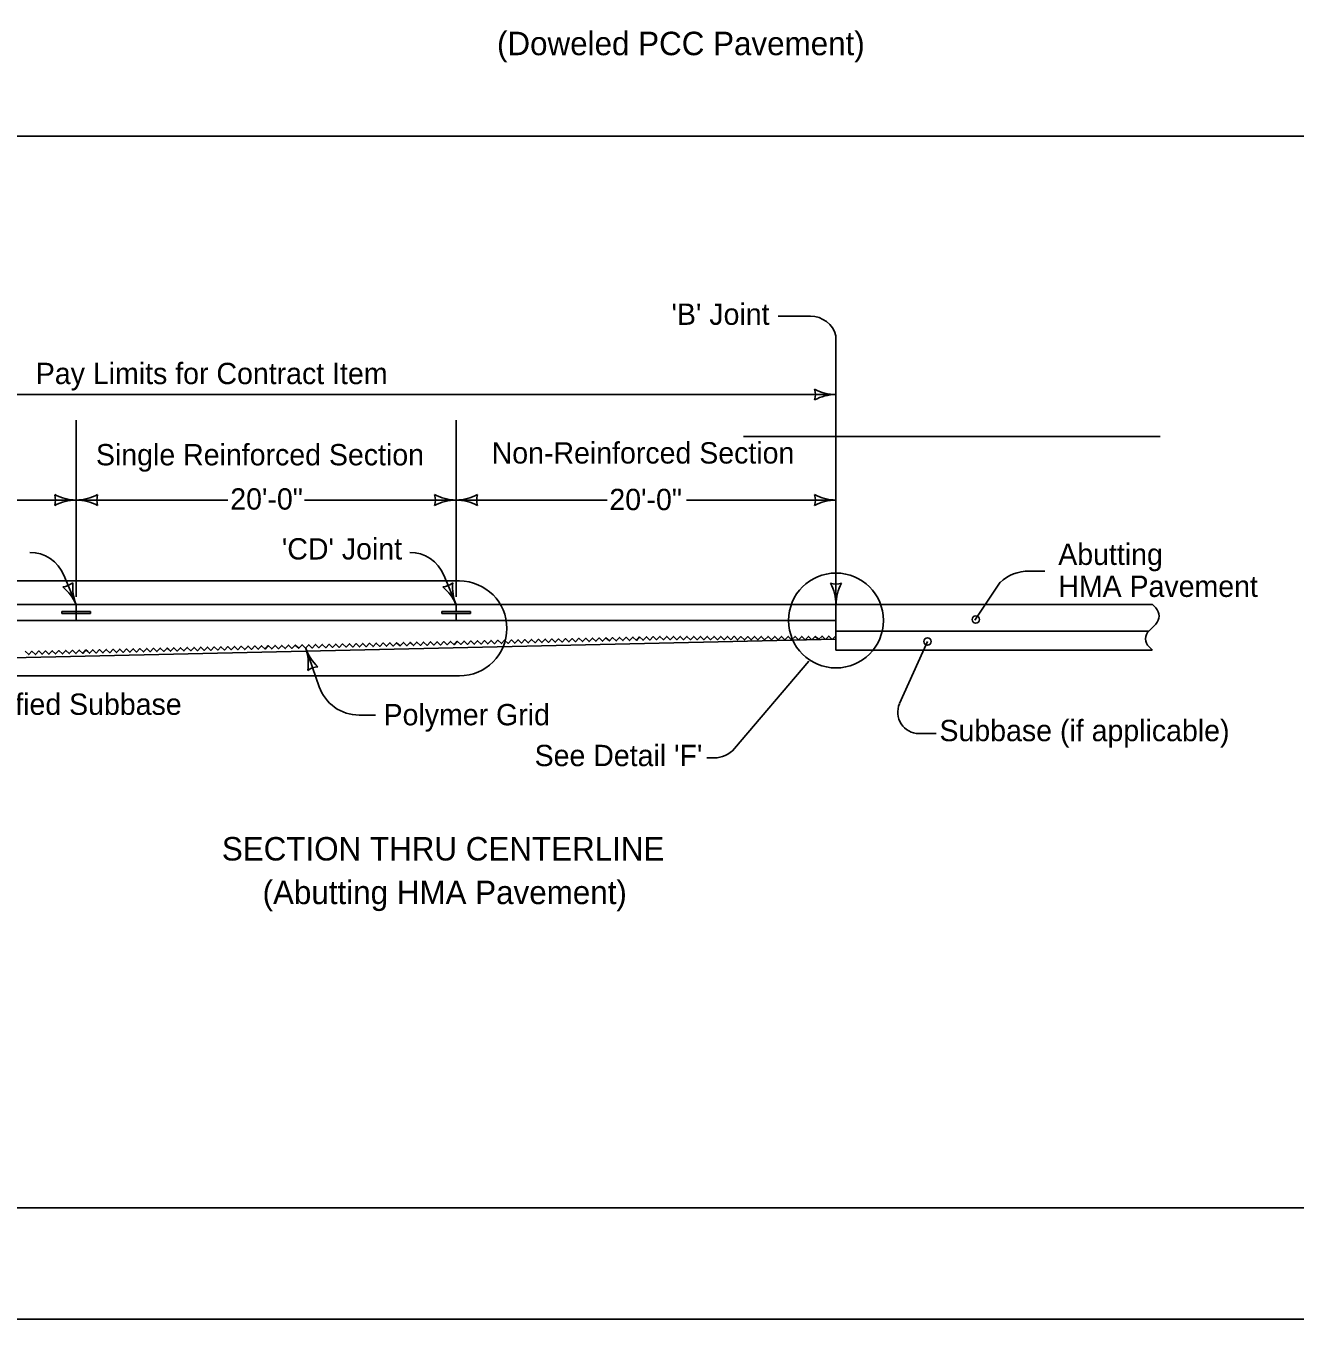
# Model space of a CAD drawing. Extents: x -2135039 to -2120895, y -2139150 to -2136566.
# Drawn here: x -2126883 to -2125693, y -2139150 to -2137937 of the extents above; entities that cross this region are included whole.
import ezdxf

# ---------------------------------------------------------------- set-up
doc = ezdxf.new("R2010")
doc.units = 0
for name, color, linetype in [('dsnDOTLogo', 7, 'Continuous'), ('dsnNonPlotable', 7, 'Continuous'), ('dsnStdDimension', 7, 'Continuous'), ('dsnStdLabel', 7, 'Continuous'), ('dsnStdLineWork', 7, 'Continuous'), ('Level 1', 7, 'Continuous'), ('Level 2', 7, 'Continuous'), ('Level 3', 7, 'Continuous')]:
    doc.layers.add(name, color=color, linetype=linetype)

msp = doc.modelspace()

# ---------------------------------------------------------------- linework, layer by layer
at = {"layer": 'dsnDOTLogo'}
msp.add_lwpolyline([(-2127839, -2139150.4), (-2124495, -2139150.4), (-2124495, -2136566.4), (-2127839, -2136566.4)], close=True, dxfattribs=at)
at = {"layer": 'dsnNonPlotable'}
msp.add_line((-2127734.5, -2138040.9), (-2124599.5, -2138040.9), dxfattribs=at)
at = {"layer": 'dsnStdDimension'}
for p, q in [((-2126622.1, -2138382.3), (-2126479.8, -2138382.3)), ((-2126479.8, -2138382.3), (-2126338, -2138382.3)), ((-2126263.7, -2138382.3), (-2126123.4, -2138382.3))]:
    msp.add_line(p, q, dxfattribs=at)
for centre, radius, start, end in [((-2126159.2, -2138283.3), 16.5, 342.2666, 17.7333), ((-2126123.4, -2138240.5), 42.7, 241.9275, 270), ((-2126123.4, -2138326), 42.7, 90, 118.0725), ((-2126515.6, -2138382.3), 16.5, 342.2666, 17.7333), ((-2126479.8, -2138339.5), 42.7, 241.9275, 270), ((-2126479.8, -2138339.5), 42.7, 270, 298.0725), ((-2126443.9, -2138382.3), 16.5, 162.2666, 197.7334), ((-2126159.2, -2138382.3), 16.5, 342.2666, 17.7333), ((-2126123.4, -2138339.5), 42.7, 241.9275, 270), ((-2126479.8, -2138425), 42.7, 90, 118.0725), ((-2126479.8, -2138425), 42.7, 61.9275, 90), ((-2126123.4, -2138425), 42.7, 90, 118.0725)]:
    msp.add_arc(centre, radius, start, end, dxfattribs=at)
at = {"layer": 'dsnStdLabel'}
for p, q in [((-2126177.7, -2138209.7), (-2126147.3, -2138209.7)), ((-2126123.4, -2138480.3), (-2126123.4, -2138228.1)), ((-2127284.7, -2138283.3), (-2126123.4, -2138283.3)), ((-2126836.2, -2138472.9), (-2126836.2, -2138307.3)), ((-2126479.8, -2138472.9), (-2126479.8, -2138307.3)), ((-2127000.6, -2138382.3), (-2126836.2, -2138382.3)), ((-2126836.2, -2138382.3), (-2126693.9, -2138382.3)), ((-2126847.7, -2138452.6), (-2126836.2, -2138480.3)), ((-2126491.3, -2138452.6), (-2126479.8, -2138480.3)), ((-2125942.3, -2138448.8), (-2125927.5, -2138448.8)), ((-2126476.6, -2138458), (-2127281.7, -2138458)), ((-2125969.3, -2138459.4), (-2125993, -2138494.9)), ((-2126608.2, -2138557.3), (-2126620.7, -2138521.3)), ((-2126063.7, -2138573.2), (-2126037.5, -2138514.9)), ((-2126148.9, -2138533.3), (-2126218.7, -2138615.3)), ((-2127281.7, -2138547.1), (-2126476.6, -2138547.1)), ((-2126555.5, -2138583.9), (-2126570.8, -2138583.9)), ((-2126029.4, -2138601.2), (-2126045.7, -2138601.2)), ((-2126237.7, -2138624.1), (-2126244.5, -2138624.1))]:
    msp.add_line(p, q, dxfattribs=at)
for centre, radius in [((-2126123.4, -2138495.2), 44.5), ((-2125992.3, -2138494.3), 3.46), ((-2126037.5, -2138514.9), 3.46)]:
    msp.add_circle(centre, radius, dxfattribs=at)
for centre, radius, start, end in [((-2126147.3, -2138234.5), 24.7, 15.0299, 90), ((-2126872, -2138382.3), 16.5, 342.2666, 17.7333), ((-2126836.2, -2138339.5), 42.7, 241.9275, 270), ((-2126836.2, -2138339.5), 42.7, 270, 298.0725), ((-2126800.3, -2138382.3), 16.5, 162.2666, 197.7334), ((-2126836.2, -2138425), 42.7, 90, 118.0725), ((-2126836.2, -2138425), 42.7, 61.9275, 90), ((-2126879.7, -2138465.9), 34.6, 22.5907, 90), ((-2126523.3, -2138465.9), 34.6, 22.5907, 90), ((-2125942.3, -2138488.4), 39.6, 90, 132.998), ((-2126850, -2138447.2), 16.5, 274.8595, 310.3262), ((-2126875.7, -2138496.7), 42.7, 22.5928, 50.6653), ((-2126796.7, -2138463.9), 42.7, 174.5203, 202.5928), ((-2126493.6, -2138447.2), 16.5, 274.8572, 310.3239), ((-2126519.3, -2138496.7), 42.7, 22.5905, 50.663), ((-2126440.3, -2138463.9), 42.7, 174.5181, 202.5905), ((-2126476.6, -2138502.6), 44.5, 270.0002, 90), ((-2126123.4, -2138444.5), 16.5, 252.2666, 287.7333), ((-2126166.1, -2138480.3), 42.7, 360, 28.0725), ((-2126080.6, -2138480.3), 42.7, 151.9275, 180), ((-2126580.4, -2138507.3), 42.7, 199.1779, 227.2504), ((-2126661.1, -2138535.4), 42.7, 351.1054, 19.1779), ((-2126609, -2138555.2), 16.5, 91.4446, 126.9113), ((-2126570.8, -2138544.3), 39.6, 199.1769, 270), ((-2126045.7, -2138581.4), 19.8, 155.762, 270)]:
    msp.add_arc(centre, radius, start, end, dxfattribs=at)
at = {"layer": 'dsnStdLineWork'}
for p, q in [((-2127281.7, -2138480.3), (-2126123.4, -2138480.3)), ((-2126836.2, -2138495.2), (-2126836.2, -2138480.3)), ((-2126123.4, -2138480.3), (-2125826.6, -2138480.3)), ((-2126123.4, -2138480.3), (-2126123.4, -2138495.2)), ((-2125841.2, -2138480.3), (-2125841.2, -2138480.3)), ((-2126123.4, -2138495.2), (-2127281.7, -2138495.2)), ((-2126123.4, -2138495.2), (-2126123.4, -2138522.9)), ((-2126123.4, -2138512.8), (-2127248, -2138538.2)), ((-2126123.4, -2138505.1), (-2125829.9, -2138505.1)), ((-2125826.8, -2138522.9), (-2126123.4, -2138522.9))]:
    msp.add_line(p, q, dxfattribs=at)
for points in [[(-2126445.3, -2138515.4), (-2126443.7, -2138517), (-2126440.6, -2138513.7), (-2126437.3, -2138516.8), (-2126434.2, -2138513.6), (-2126431, -2138516.7), (-2126427.9, -2138513.4), (-2126424.7, -2138516.5), (-2126421.6, -2138513.3), (-2126418.3, -2138516.4), (-2126415.2, -2138513.1), (-2126412, -2138516.2), (-2126408.9, -2138513), (-2126405.7, -2138516.1), (-2126402.6, -2138512.8), (-2126399.3, -2138515.9), (-2126396.2, -2138512.7), (-2126393, -2138515.8), (-2126389.9, -2138512.5), (-2126386.7, -2138515.6), (-2126383.6, -2138512.4), (-2126380.3, -2138515.5), (-2126377.2, -2138512.2), (-2126374, -2138515.3), (-2126370.9, -2138512.1), (-2126369.3, -2138513.6)], [(-2126369.3, -2138513.6), (-2126367.6, -2138515.2), (-2126364.6, -2138511.9), (-2126361.3, -2138515), (-2126358.2, -2138511.8), (-2126355, -2138514.9), (-2126351.9, -2138511.7), (-2126348.6, -2138514.7), (-2126345.6, -2138511.5), (-2126342.3, -2138514.6), (-2126339.2, -2138511.4), (-2126336, -2138514.4), (-2126332.9, -2138511.2), (-2126329.6, -2138514.3), (-2126326.6, -2138511.1), (-2126323.3, -2138514.1), (-2126320.2, -2138510.9), (-2126317, -2138514), (-2126313.9, -2138510.8), (-2126310.6, -2138513.9), (-2126307.6, -2138510.6), (-2126304.3, -2138513.7), (-2126301.2, -2138510.5), (-2126298, -2138513.6), (-2126294.9, -2138510.3), (-2126293.3, -2138511.9)], [(-2126293.3, -2138511.7), (-2126291.7, -2138513.3), (-2126288.5, -2138510.1), (-2126285.3, -2138513.3), (-2126282.2, -2138510.1), (-2126279, -2138513.3), (-2126275.8, -2138510.1), (-2126272.7, -2138513.3), (-2126269.5, -2138510.1), (-2126266.3, -2138513.3), (-2126263.2, -2138510.1), (-2126260, -2138513.3), (-2126256.8, -2138510.1), (-2126253.7, -2138513.3), (-2126250.5, -2138510.1), (-2126247.3, -2138513.2), (-2126244.2, -2138510.1), (-2126241, -2138513.2), (-2126237.8, -2138510.1), (-2126234.7, -2138513.2), (-2126231.5, -2138510.1), (-2126228.3, -2138513.2), (-2126225.2, -2138510.1), (-2126222, -2138513.2), (-2126218.8, -2138510), (-2126217.2, -2138511.6)], [(-2126217.2, -2138511.9), (-2126215.7, -2138513.4), (-2126212.5, -2138510.3), (-2126209.3, -2138513.4), (-2126206.2, -2138510.3), (-2126203, -2138513.4), (-2126199.8, -2138510.2), (-2126196.6, -2138513.4), (-2126193.5, -2138510.2), (-2126190.3, -2138513.4), (-2126187.1, -2138510.2), (-2126184, -2138513.4), (-2126180.8, -2138510.2), (-2126177.6, -2138513.4), (-2126174.5, -2138510.2), (-2126171.3, -2138513.4), (-2126168.1, -2138510.2), (-2126165, -2138513.4), (-2126161.8, -2138510.2), (-2126158.6, -2138513.4), (-2126155.5, -2138510.2), (-2126152.3, -2138513.4), (-2126149.1, -2138510.2), (-2126146, -2138513.3), (-2126142.8, -2138510.2), (-2126141.2, -2138511.8)], [(-2126141.2, -2138511.4), (-2126139.7, -2138513), (-2126136.5, -2138509.8), (-2126133.3, -2138513), (-2126130.2, -2138509.8), (-2126127, -2138513), (-2126123.8, -2138509.8), (-2126123.4, -2138510.3)], [(-2126884, -2138524.1), (-2126880.7, -2138527.2), (-2126877.6, -2138524), (-2126874.4, -2138527.1), (-2126871.3, -2138523.8), (-2126868.1, -2138526.9), (-2126865, -2138523.7), (-2126861.7, -2138526.8), (-2126858.6, -2138523.5), (-2126855.4, -2138526.6), (-2126852.3, -2138523.4), (-2126849.1, -2138526.5), (-2126846, -2138523.2), (-2126842.7, -2138526.3), (-2126839.6, -2138523.1), (-2126836.4, -2138526.2), (-2126833.3, -2138522.9), (-2126830, -2138526), (-2126827, -2138522.8), (-2126825.3, -2138524.3)], [(-2126825.3, -2138524.3), (-2126823.7, -2138525.9), (-2126820.6, -2138522.6), (-2126817.4, -2138525.7), (-2126814.3, -2138522.5), (-2126811, -2138525.6), (-2126808, -2138522.3), (-2126804.7, -2138525.4), (-2126801.6, -2138522.2), (-2126798.4, -2138525.3), (-2126795.3, -2138522), (-2126792, -2138525.1), (-2126789, -2138521.9), (-2126785.7, -2138525), (-2126782.6, -2138521.7), (-2126779.4, -2138524.8), (-2126776.3, -2138521.6), (-2126773, -2138524.7), (-2126769.9, -2138521.4), (-2126766.7, -2138524.5), (-2126763.6, -2138521.3), (-2126760.4, -2138524.4), (-2126757.3, -2138521.1), (-2126754, -2138524.2), (-2126750.9, -2138521), (-2126749.3, -2138522.5)], [(-2126749.3, -2138522.5), (-2126747.7, -2138524.1), (-2126744.6, -2138520.8), (-2126741.4, -2138523.9), (-2126738.3, -2138520.7), (-2126735, -2138523.8), (-2126731.9, -2138520.5), (-2126728.7, -2138523.6), (-2126725.6, -2138520.4), (-2126722.4, -2138523.5), (-2126719.3, -2138520.2), (-2126716, -2138523.3), (-2126712.9, -2138520.1), (-2126709.7, -2138523.2), (-2126706.6, -2138519.9), (-2126703.4, -2138523), (-2126700.3, -2138519.8), (-2126697, -2138522.9), (-2126693.9, -2138519.6), (-2126690.7, -2138522.7), (-2126687.6, -2138519.5), (-2126684.4, -2138522.6), (-2126681.3, -2138519.3), (-2126678, -2138522.4), (-2126674.9, -2138519.2), (-2126673.3, -2138520.7)], [(-2126673.3, -2138520.8), (-2126671.7, -2138522.3), (-2126668.6, -2138519.1), (-2126665.4, -2138522.2), (-2126662.3, -2138518.9), (-2126659, -2138522), (-2126655.9, -2138518.8), (-2126652.7, -2138521.9), (-2126649.6, -2138518.6), (-2126646.4, -2138521.7), (-2126643.3, -2138518.5), (-2126640, -2138521.6), (-2126636.9, -2138518.3), (-2126633.7, -2138521.4), (-2126630.6, -2138518.2), (-2126627.4, -2138521.3), (-2126624.3, -2138518), (-2126621, -2138521.1), (-2126617.9, -2138517.9), (-2126614.7, -2138521), (-2126611.6, -2138517.7), (-2126608.4, -2138520.8), (-2126605.3, -2138517.6), (-2126602, -2138520.7), (-2126598.9, -2138517.4), (-2126597.3, -2138519)], [(-2126597.3, -2138519), (-2126595.7, -2138520.5), (-2126592.6, -2138517.3), (-2126589.3, -2138520.4), (-2126586.3, -2138517.1), (-2126583, -2138520.2), (-2126579.9, -2138517), (-2126576.7, -2138520.1), (-2126573.6, -2138516.8), (-2126570.3, -2138519.9), (-2126567.3, -2138516.7), (-2126564, -2138519.8), (-2126560.9, -2138516.6), (-2126557.7, -2138519.6), (-2126554.6, -2138516.4), (-2126551.3, -2138519.5), (-2126548.3, -2138516.3), (-2126545, -2138519.4), (-2126541.9, -2138516.1), (-2126538.7, -2138519.2), (-2126535.6, -2138516), (-2126532.3, -2138519), (-2126529.2, -2138515.8), (-2126526, -2138518.9), (-2126522.9, -2138515.7), (-2126521.3, -2138517.2)], [(-2126521.3, -2138517.2), (-2126519.7, -2138518.8), (-2126516.6, -2138515.5), (-2126513.3, -2138518.6), (-2126510.2, -2138515.4), (-2126507, -2138518.5), (-2126503.9, -2138515.2), (-2126500.7, -2138518.3), (-2126497.6, -2138515.1), (-2126494.3, -2138518.2), (-2126491.2, -2138514.9), (-2126488, -2138518), (-2126484.9, -2138514.8), (-2126481.7, -2138517.9), (-2126478.6, -2138514.6), (-2126475.3, -2138517.7), (-2126472.2, -2138514.5), (-2126469, -2138517.6), (-2126465.9, -2138514.3), (-2126462.7, -2138517.4), (-2126459.6, -2138514.2), (-2126456.3, -2138517.3), (-2126453.2, -2138514), (-2126450, -2138517.1), (-2126446.9, -2138513.9), (-2126445.3, -2138515.4)]]:
    msp.add_lwpolyline(points, dxfattribs=at)
at = {"layer": 'Level 1'}
msp.add_lwpolyline([(-2127734.5, -2137035.9), (-2124599.5, -2137035.9), (-2124599.5, -2139045.9), (-2127734.5, -2139045.9)], close=True, dxfattribs=at)
at = {"layer": 'Level 2'}
for p, q in [((-2126210.1, -2138322.7), (-2125819.2, -2138322.7)), ((-2126849.5, -2138486.8), (-2126822.8, -2138486.8)), ((-2126849.5, -2138488.7), (-2126822.8, -2138488.7)), ((-2126836.2, -2138495.2), (-2126836.2, -2138480.3)), ((-2126822.8, -2138486.8), (-2126822.8, -2138488.7)), ((-2126493.1, -2138486.8), (-2126466.4, -2138486.8)), ((-2126493.1, -2138488.7), (-2126466.4, -2138488.7)), ((-2126123.4, -2138480.3), (-2126479.8, -2138480.3)), ((-2126479.8, -2138480.3), (-2126479.8, -2138486.8)), ((-2126479.8, -2138486.8), (-2126466.4, -2138486.8)), ((-2126466.4, -2138488.7), (-2126479.8, -2138488.7)), ((-2126479.8, -2138488.7), (-2126479.8, -2138495.2)), ((-2126479.8, -2138488.7), (-2126479.8, -2138495.2)), ((-2126466.4, -2138486.8), (-2126466.4, -2138488.7)), ((-2126466.4, -2138486.8), (-2126466.4, -2138488.7)), ((-2126123.4, -2138495.2), (-2126123.4, -2138480.3)), ((-2125823.5, -2138483.4), (-2125826.6, -2138480.3)), ((-2126479.8, -2138495.2), (-2126123.4, -2138495.2)), ((-2125829.7, -2138504.8), (-2125823.5, -2138498.6)), ((-2125826.6, -2138523.1), (-2125829.7, -2138520))]:
    msp.add_line(p, q, dxfattribs=at)
for centre, radius, start, end in [((-2125831, -2138491), 10.7, 315, 45), ((-2125822.2, -2138512.4), 10.7, 135, 225), ((-2126237.7, -2138599.1), 25, 270, 319.6052)]:
    msp.add_arc(centre, radius, start, end, dxfattribs=at)
at = {"layer": 'Level 3'}
for p, q in [((-2127281.7, -2138480.3), (-2126836.2, -2138480.3)), ((-2126836.2, -2138486.8), (-2126849.5, -2138486.8)), ((-2126849.5, -2138486.8), (-2126849.5, -2138488.7)), ((-2126822.8, -2138486.8), (-2126849.5, -2138486.8)), ((-2126849.5, -2138486.8), (-2126836.2, -2138486.8)), ((-2126849.5, -2138486.8), (-2126849.5, -2138488.7)), ((-2126849.5, -2138488.7), (-2126836.2, -2138488.7)), ((-2126836.2, -2138480.3), (-2126836.2, -2138486.8)), ((-2126836.2, -2138486.8), (-2126836.2, -2138480.3)), ((-2126836.2, -2138480.3), (-2126479.8, -2138480.3)), ((-2126822.8, -2138486.8), (-2126836.2, -2138486.8)), ((-2126836.2, -2138488.7), (-2126836.2, -2138495.2)), ((-2126836.2, -2138495.2), (-2126836.2, -2138488.7)), ((-2126836.2, -2138488.7), (-2126822.8, -2138488.7)), ((-2126822.8, -2138488.7), (-2126822.8, -2138486.8)), ((-2126479.8, -2138486.8), (-2126493.1, -2138486.8)), ((-2126493.1, -2138486.8), (-2126493.1, -2138488.7)), ((-2126493.1, -2138486.8), (-2126493.1, -2138488.7)), ((-2126493.1, -2138488.7), (-2126479.8, -2138488.7)), ((-2126479.8, -2138480.3), (-2126479.8, -2138486.8)), ((-2126479.8, -2138486.8), (-2126479.8, -2138480.3)), ((-2126466.4, -2138486.8), (-2126479.8, -2138486.8)), ((-2126479.8, -2138488.7), (-2126479.8, -2138495.2)), ((-2126836.2, -2138495.2), (-2127244.6, -2138495.2)), ((-2126479.8, -2138495.2), (-2126836.2, -2138495.2))]:
    msp.add_line(p, q, dxfattribs=at)

# ---------------------------------------------------------------- texts
at = {"layer": 'dsnStdDimension'}
for s, p in [('Non-Reinforced Section', (-2126446.4, -2138348)), ('20\'-0"', (-2126691.6, -2138391.2)), ('20\'-0"', (-2126336, -2138391.7))]:
    msp.add_text(s, height=20, dxfattribs=at).set_placement(p)
at = {"layer": 'dsnStdLabel'}
for s, p in [("'B' Joint", (-2126277.7, -2138217.9)), ('Pay Limits for Contract Item', (-2126874, -2138273.5)), ('Single Reinforced Section', (-2126817.6, -2138349.7)), ("'CD' Joint", (-2126643.2, -2138438)), ('Abutting', (-2125914.9, -2138443.1)), ('HMA Pavement', (-2125914.9, -2138473.1)), ('Modified Subbase', (-2126951.3, -2138583.7)), ('Polymer Grid', (-2126547.8, -2138593.5)), ('Subbase (if applicable)', (-2126026.3, -2138608.4)), ("See Detail 'F'", (-2126406.1, -2138631.8))]:
    msp.add_text(s, height=20, dxfattribs=at).set_placement(p)
at = {"layer": 'dsnStdLineWork'}
for s, p in [('(Doweled PCC Pavement)', (-2126441.4, -2137965)), ('(Abutting HMA Pavement)', (-2126661.3, -2138761.2))]:
    msp.add_text(s, height=22, dxfattribs=at).set_placement(p)
at = {"layer": 'Level 3'}
msp.add_text('SECTION THRU CENTERLINE', height=22, dxfattribs=at).set_placement((-2126699.5, -2138720.3))

doc.saveas('drawing.dxf')
